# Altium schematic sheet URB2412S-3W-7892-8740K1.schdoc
size 277 x 190 mm; Device: default297x210; Symbol: default297x210; Name: default297x210; Date: 2026.03.04; Size: "A4"; Id: /; File: URB2412S-3W-7892-8740K1; Sheet: /
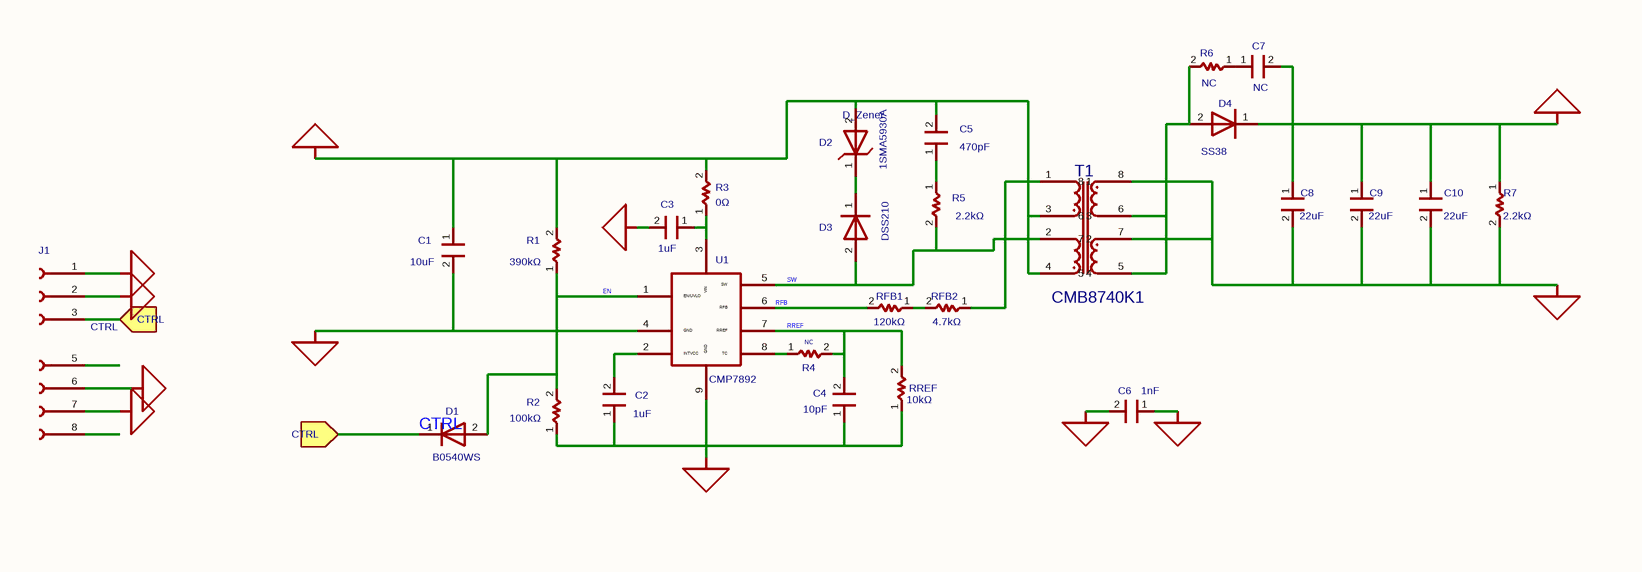
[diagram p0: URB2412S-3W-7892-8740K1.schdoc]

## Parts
C1  10uF  [coileasy:C_1206]
C2  1uF  [coileasy:C_0603]
C3  1uF  [coileasy:C_0603]
C4  10pF  [coileasy:C_0603]
C5  470pF  [coileasy:C_0603]
C6  1nF  [coileasy:C_1206]
C7  value NC  [coileasy:C_0603]  (hidden comment: My_library_C)
C8  22uF  [coileasy:C_1206]
C9  22uF  [coileasy:C_1206]
C10  22uF  [coileasy:C_1206]
D1  B0540WS  [coileasy:SOD-323]
D2  value D_Zener  [coileasy:SMA]  (hidden comment: 1SMA5930A)
D3  DSS210  [coileasy:SOD-123FL]
D4  SS38  [coileasy:SMA]
J1  Coileasy_Conn_01x07_1  [coileasy:PinHeader_01x07_1_P2.54mm_Vertical]  (value not drawn)
R1  390kΩ  [R0603]
R2  100kΩ  [coileasy:R_0603]
R3  0Ω  [coileasy:R_0603]
R4  value NC  [coileasy:R_0603]  (hidden comment: Coileasy_R)
R5  2.2kΩ  [R0805]
R6  value NC  [coileasy:R_0603]  (hidden comment: Coileasy_R)
R7  2.2kΩ  [coileasy:R_0805]
RFB1  120kΩ  [coileasy:R_0603]
RFB2  4.7kΩ  [coileasy:R_0603]
RREF  10kΩ  [coileasy:R_0603]
T1  CMB8740K1  [CMB8740K1]
U1  CMP7892  [coileasy:ESOP-8]

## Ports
CTRL (in)

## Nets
GND1: C1.2 C2.1 C3.2 C4.1 C6.2 J1.1(Pin_1) R2.1 RREF.1 U1.4(GND) U1.9(GND)
GND2: C6.1 C8.2 C9.2 C10.2 J1.7(Pin_7) R7.2 T1.7 T1.8
VIN: C1.1 C5.2 D2.2(A) J1.2(Pin_2) R1.2 R3.2 T1.3 T1.4
VOUT: C7.2 C8.1 C9.1 C10.1 D4.1(K) J1.6(Pin_6) R7.1
CTRL: D1.1(K) J1.3(Pin_3) ; port CTRL
EN: D1.2(A) R1.1 R2.2 U1.1(EN/UVLO)
RFB: RFB1.2 U1.6(RFB)
RREF: C4.2 R4.2 RREF.2 U1.7(RREF)
SW: D3.2(A) R5.2 RFB2.1 T1.1 T1.2 U1.5(SW)
NetC2_2: C2.2 U1.2(INTVCC)
NetC3_1: C3.1 R3.1 U1.3(VIN)
NetC5_1: C5.1 R5.1
NetC7_1: C7.1 R6.1
NetD2_1: D2.1(K) D3.1(K)
NetD4_2: D4.2(A) R6.2 T1.5 T1.6
NetR4_1: R4.1 U1.8(TC)
NetRFB1_1: RFB1.1 RFB2.2

Not connected (* = marked no-connect by the designer): J1 5(Pin_5) 8(Pin_8)

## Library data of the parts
C1 = CL31A106KBHNNNE: 容值:10uF;精度:±10%;额定电压:50V;温度系数:X5R;; Manufacturer: SAMSUNG(三星); Symbol: MY_C; Add into BOM: yes; 3D Model: e4be705b945545a48e666415e3682bd8; 3D Model Transform: 125.984,62.992,0,0,0,0,0,0,0; Tolerance: ±10%; Voltage Rating: 50V; Temperature Coefficient: X5R; ki_keywords: cap capacitor; ki_fp_filters: C_*; ModelName: C1206_L3.2-W1.6-H1.3
C2 = 0603X105K500NT: 容值:1uF;精度:±10%;额定电压:50V;温度系数:X5R;; Manufacturer: FH(风华); Symbol: MY_C; Add into BOM: yes; 3D Model: ac125912035d415993ca9572d50418b1; 3D Model Transform: 62.992,31.496,0,0,0,0,0,0,0; Tolerance: ±10%; Voltage Rating: 50V; Temperature Coefficient: X5R; ki_keywords: cap capacitor; ki_fp_filters: C_*; UniqueId: 21d50210554cb61f; ModelName: C0603_L1.6-W0.8-H0.8
C3 = 0603X105K500NT: 容值:1uF;精度:±10%;额定电压:50V;温度系数:X5R;; Manufacturer: FH(风华); Symbol: MY_C; Add into BOM: yes; 3D Model: ac125912035d415993ca9572d50418b1; 3D Model Transform: 62.992,31.496,0,0,0,0,0,0,0; Tolerance: ±10%; Voltage Rating: 50V; Temperature Coefficient: X5R; ki_keywords: cap capacitor; ki_fp_filters: C_*; UniqueId: ec64484c8c07847f; ModelName: C0603_L1.6-W0.8-H0.8
C4 = CC0603JRNPO9BN100: 容值:10pF;精度:±5%;额定电压:50V;温度系数:NP0;; Manufacturer: YAGEO(国巨); Symbol: My_library_C; Add into BOM: yes; 3D Model: ac125912035d415993ca9572d50418b1; 3D Model Transform: 62.992,31.496,0,0,0,0,0,0,0; Tolerance: ±5%; Voltage Rating: 50V; Temperature Coefficient: NP0; ki_keywords: cap capacitor; ki_fp_filters: C_*; UniqueId: 623e2bb2442f04df; ModelName: C0603_L1.6-W0.8-H0.8
C5 = CC0603KRX7R9BB471: 容值:470pF;精度:±10%;额定电压:50V;材质(温度系数):X7R;; Manufacturer: YAGEO(国巨); Symbol: My_library_C; Add into BOM: yes; 3D Model: ac125912035d415993ca9572d50418b1; 3D Model Transform: 62.992,31.496,0,0,0,0,0,0,0; Tolerance: ±10%; Voltage Rated: 50V; Temperature Coefficient: X7R; ki_keywords: cap capacitor; ki_fp_filters: C_*; ModelName: C0603_L1.6-W0.8-H0.8
C6 = CC1206KKX7RDBB102: 容值:1nF;精度:±10%;额定电压:2kV;温度系数:X7R;; Manufacturer: YAGEO(国巨); Symbol: MY_C; Add into BOM: yes; 3D Model: e4be705b945545a48e666415e3682bd8; 3D Model Transform: 125.984,62.992,0,0,0,0,0,0,0; Tolerance: ±10%; Voltage Rating: 2kV; Temperature Coefficient: X7R; ki_keywords: cap capacitor; ki_fp_filters: C_*; ModelName: C1206_L3.2-W1.6-H1.3
C7 = My_library_C: Add into BOM: no; ki_keywords: cap capacitor; ki_fp_filters: C_*; UniqueId: 3007ca2539a35480
C8-C10 = CL31A226KAHNNNE: 容值:22uF;精度:±10%;额定电压:25V;温度系数:X5R;; Manufacturer: SAMSUNG(三星); Symbol: MY_C; Add into BOM: yes; 3D Model: e4be705b945545a48e666415e3682bd8; 3D Model Transform: 125.984,62.992,0,0,0,0,0,0,0; Tolerance: ±10%; Voltage Rating: 25V; Temperature Coefficient: X5R; ki_keywords: cap capacitor; ki_fp_filters: C_*; ModelName: C1206_L3.2-W1.6-H1.3
D1 = B0540WS_C475613: 二极管配置:独立式;正向压降(Vf):600mV@200mA;直流反向耐压(Vr):40V;整流电流:350mA;; Manufacturer: SHIKUES(时科); Symbol: Coileasy library_D; Add into BOM: yes; 3D Model: 7459fe65e23146c0a8d836e46a0add72; 3D Model Transform: 104.3305,51.181,0,0,0,0,0,0,0; Diode Configuration: 独立式; Voltage - DC Reverse(Vr): 40V; Current - Rectified: 350mA; Reverse Leakage Current (Ir): 5uA@30V; Non-Repetitive Peak Forward Surge Current: 1.5A; Value: D; ki_keywords: diode; ki_fp_filters: TO-???* *_Diode_* *SingleDiode* D_*; ModelName: SOD-323_L1.8-W1.3-LS2.5-RD
D2 = 1SMA5930A: 二极管配置:独立式;稳压值(标称值):16V;稳压值(范围):14.4V~17.6V;耗散功率(Pd):1.5W;; Manufacturer: LGE(鲁光); Symbol: My library_D_Zener; Add into BOM: yes; 3D Model: e3551acb3c5a4975a5e9d36087fe1fa2; 3D Model Transform: 185.039,102.362,0,0,0,0,0,0,0; Diode Configuration: 独立式; Zener Voltage(Nom): 16V; Reverse Leakage Current (Ir): 1uA@12.2V; Pd - Power Dissipation: 1.5W; Impedance(Zzt): 10Ω; Impedance(Zzk): 600Ω; Operating Junction Temperature Range: -55℃~+150℃; ki_keywords: diode; ki_fp_filters: TO-???* *_Diode_* *SingleDiode* D_*; ModelName: SMA_L4.3-W2.6-LS5.2-RD
D3 = DSS210: 二极管配置:独立式;正向压降(Vf):850mV@2A;直流反向耐压(Vr):100V;整流电流:2A;; Manufacturer: CJ(江苏长电/长晶); Symbol: My library_DSS210; Add into BOM: yes; 3D Model: 125b22121bda4d3999c0a2016797619b; 3D Model Transform: 145.669,70.866,0,0,0,0,0,0,0; Diode Configuration: 独立式; Voltage - DC Reverse(Vr): 100V; Current - Rectified: 2A; Reverse Leakage Current (Ir): 100uA@100V; Operating Junction Temperature Range: -55℃~+150℃; Non-Repetitive Peak Forward Surge Current: 40A; Value: SL56; ki_keywords: diode; ki_fp_filters: TO-???* *_Diode_* *SingleDiode* D_*; ModelName: SOD-123_L2.8-W1.8-H1.4-LS3.7
D4 = SS38_C64999: 二极管配置:独立式;正向压降(Vf):700mV@3A;直流反向耐压(Vr):80V;整流电流:3A;; Manufacturer: MDD(辰达半导体); Symbol: My library_DSS210; Add into BOM: yes; 3D Model: 4f1e9ef2303f48b48aa8ce0cacf8d7b1; 3D Model Transform: 204.724,102.362,0,0,0,0,0,0,0; Diode Configuration: 独立式; Voltage - DC Reverse(Vr): 80V; Current - Rectified: 3A; Reverse Leakage Current (Ir): 500uA@80V; Operating Junction Temperature Range: -55℃~+125℃; Value: SL56; ki_keywords: diode; ki_fp_filters: TO-???* *_Diode_* *SingleDiode* D_*; UniqueId: gge1; ModelName: SMA_L4.4-W2.8-LS5.4-RD
J1 = Coileasy_Conn_01x07_1: Value: Conn_01x08-1; ki_keywords: connector; ki_fp_filters: Connector*:*_1x??_*; Origin Footprint: library:PinHeader_01x07_P2.54mm_Vertical; UniqueId: 9f49826860c2c79d; AddInBom: yes
R1 = RC0603FR-07390KL: 电阻类型:厚膜电阻;阻值:390kΩ;精度:±1%;功率:100mW;最大工作电压:75V;温度系数:±100ppm/℃;; Manufacturer: YAGEO(国巨); Symbol: Coileasy_R; Add into BOM: yes; 3D Model: fc143cca1e79419f9cd78b61e9279f08; 3D Model Transform: 31.8897,63.7794,0,90,0,0,0,0,0; Tolerance: ±1%; Power(Watts): 100mW; Overload Voltage (Max): 75V; ki_keywords: R res resistor; ki_fp_filters: R_*; UniqueId: 4e166b190d4de1c3
R2 = RC0603FR-07100KL: 电阻类型:厚膜电阻;阻值:100kΩ;精度:±1%;功率:100mW;最大工作电压:75V;温度系数:±100ppm/℃;; Manufacturer: YAGEO(国巨); Symbol: Coileasy_R; Add into BOM: yes; 3D Model: fc143cca1e79419f9cd78b61e9279f08; 3D Model Transform: 31.8897,63.7794,0,90,0,0,0,0,0; Tolerance: ±1%; Power(Watts): 100mW; Overload Voltage (Max): 75V; ki_keywords: R res resistor; ki_fp_filters: R_*; ModelName: R0603
R3 = RC0603FR-070RL: 电阻类型:厚膜电阻;阻值:0Ω;精度:±1%;功率:100mW;工作电压:75V;温度系数:-;; Manufacturer: YAGEO(国巨); Symbol: Coileasy_R; Add into BOM: yes; 3D Model: fc143cca1e79419f9cd78b61e9279f08; 3D Model Transform: 31.8897,63.7794,0,90,0,0,0,0,0; Tolerance: ±1%; Power(Watts): 100mW; Voltage-Supply(Max): 75V; ki_keywords: R res resistor; ki_fp_filters: R_*; UniqueId: 6e26aea592918673; ModelName: R0603
R4 = Coileasy_R: Resistor; Add into BOM: no; ki_keywords: R res resistor; ki_fp_filters: R_*; UniqueId: 49359f7360e76581
R5 R7 = RC0805FR-072K2L: 电阻类型:厚膜电阻;阻值:2.2kΩ;精度:±1%;功率:125mW;工作电压:150V;温度系数:±100ppm/℃;; Manufacturer: YAGEO(国巨); Symbol: Coileasy_R; Add into BOM: yes; 3D Model: 37a81e68749a4138bd2dfa6897b24b85; 3D Model Transform: 78.74,51.181,0,0,0,0,0,-0.0005,0; Tolerance: ±1%; Power(Watts): 125mW; Voltage-Supply(Max): 150V; ki_keywords: R res resistor; ki_fp_filters: R_*; ModelName: R0805_L2.0-W1.3-H0.6
R6 = Coileasy_R: Resistor; Add into BOM: no; ki_keywords: R res resistor; ki_fp_filters: R_*; UniqueId: c9a24d22ca7022dc
RFB1 = RC0603FR-07120KL: 电阻类型:厚膜电阻;阻值:120kΩ;精度:±1%;功率:100mW;工作电压:75V;温度系数:±100ppm/℃;; Manufacturer: YAGEO(国巨); Symbol: Coileasy_R; Add into BOM: yes; 3D Model: fc143cca1e79419f9cd78b61e9279f08; 3D Model Transform: 31.8897,63.7794,0,90,0,0,0,0,0; Tolerance: ±1%; Power(Watts): 100mW; Voltage-Supply(Max): 75V; ki_keywords: R res resistor; ki_fp_filters: R_*; UniqueId: 0c9fe0d7ec7ae194; ModelName: R0603
RFB2 = RC0603FR-074K7L: 电阻类型:厚膜电阻;阻值:4.7kΩ;精度:±1%;功率:100mW;工作电压:75V;温度系数:±100ppm/℃;; Manufacturer: YAGEO(国巨); Symbol: Coileasy_R; Add into BOM: yes; 3D Model: fc143cca1e79419f9cd78b61e9279f08; 3D Model Transform: 31.8897,63.7794,0,90,0,0,0,0,0; Tolerance: ±1%; Power(Watts): 100mW; Voltage-Supply(Max): 75V; ki_keywords: R res resistor; ki_fp_filters: R_*; UniqueId: bc10ee0fef73f830; ModelName: R0603
RREF = RC0603FR-0710KL: 电阻类型:厚膜电阻;阻值:10kΩ;精度:±1%;功率:100mW;最大工作电压:75V;温度系数:±100ppm/℃;; Manufacturer: YAGEO(国巨); Symbol: Coileasy_R; Add into BOM: yes; 3D Model: fc143cca1e79419f9cd78b61e9279f08; 3D Model Transform: 31.8897,63.7794,0,90,0,0,0,0,0; Tolerance: ±1%; Power(Watts): 100mW; Overload Voltage (Max): 75V; ki_keywords: R res resistor; ki_fp_filters: R_*; ModelName: R0603
T1 = CMB8740K1: AddInBom: yes
U1 = CMP7892: Manufacturer: coileasy(线易); Symbol: Coileasy_CMP7892; Add into BOM: yes; 3D Model: f43fc10339aa42ce991094e4756959b9; 3D Model Transform: 192.913,236.22,0,0,0,0,0,0,0; UniqueId: 48a4a086d8c42a18; ModelName: ESOP-8_L4.9-W3.9-P1.27-LS6.0-BL-EP3.3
